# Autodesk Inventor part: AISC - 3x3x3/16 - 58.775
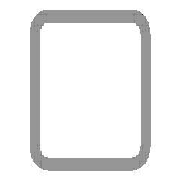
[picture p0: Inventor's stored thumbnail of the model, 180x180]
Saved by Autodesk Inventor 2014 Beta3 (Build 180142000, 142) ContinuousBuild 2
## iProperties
_CCFamilyMember: 9
_CCFamilyDisplayName: ANSI AISC (Square) - Tube
_FrameMemberDoc: Frame Member File
_Version: 15.0.0
_GetPNFromCC: 1
Created: 2011-01
Part Number: AISC - 3x3x3/16 - 58.775
Material: Steel, Mild
Description: Tube
Document SubType Name: Modeling
Standard: ANSI
Designer: Beta-8540w
Standards Organization: ANSI
Language: en-US
Size Designation: 3x3x3/16
Categories: <MemberInstance><Categories><Category DisplayName="Structural Shapes" InternalName="089c4875-fa83-4c05-b084-43b9cc11f5ed" Mnemonic="GRDR"><CategoryParameter Dis
Stock Number: 3x3x3/16
Density: 7.86 g/cm^3
Appearance: Steel
IsCustomPart: 1
G_L: 58.775 in
G_W: 3.000 in
G_H: 3.000 in
+E0C39BE0-1588-4A7D-93DD-AA65CE2CC4A8+CUTDETAIL1: Cut
Author: Beta-8540w
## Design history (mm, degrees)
node "Start plane"
node "End plane"
sketch "Sketch"
  geometry: L1 (-38.1, -28.575)-(-38.1, 28.575); L2 (-28.575, 38.1)-(28.575, 38.1); L3 (38.1, 28.575)-(38.1, -28.575); L4 (28.575, -38.1)-(-28.575, -38.1); L5 (-28.575, 33.337)-(28.575, 33.338); L6 (33.338, 28.575)-(33.338, -28.575); L7 (28.575, -33.337)-(-28.575, -33.338); L8 (-33.338, -28.575)-(-33.338, 28.575); L9 (0, 56.102)-(0, -56.102) reference; L10 (-56.102, 0)-(56.102, 0) reference; A1 r 9.525 centre (-28.575, -28.575) between (-38.1, -28.575) and (-28.575, -38.1); A2 r 9.525 centre (-28.575, 28.575) between (-28.575, 38.1) and (-38.1, 28.575); A3 r 9.525 centre (28.575, 28.575) between (38.1, 28.575) and (28.575, 38.1); A4 r 9.525 centre (28.575, -28.575) between (28.575, -38.1) and (38.1, -28.575); A5 r 4.763 centre (-28.575, 28.575) between (-28.575, 33.337) and (-33.338, 28.575); A6 r 4.763 centre (28.575, 28.575) between (33.338, 28.575) and (28.575, 33.338); A7 r 4.763 centre (28.575, -28.575) between (28.575, -33.337) and (33.338, -28.575); A8 r 4.763 centre (-28.575, -28.575) between (-33.338, -28.575) and (-28.575, -33.338)
  constraints: 16 end point, 16 point on circle, 8 centre point, 8 tangent, 4 parallel, 3 equal radius, 2 perpendicular, 7 other
  dimensions: "d10" = 76.2 distance between parallel lines of L2 L4 (= G_H); "d11" = 76.2 distance between parallel lines of L1 L3 (= G_W); "d12" = 4.7625 distance between parallel lines of L3 L6 (= G_T); "d15" = 38.1 distance between parallel lines of L2 L10 (= 0.5 x d10); "d16" = 38.1 distance between parallel lines of L9 L3 (= 0.5 x d11); "d17" = 9.525 radius of A1 (= G_IR)
extrude "Body" new body sketch "Sketch" stored distance "d3" = 1492.89148 (= G_L); taper "d4" = 0 deg
node "Driven Length"
  sketch "Sketch3"
    geometry: L1 (0, 0)-(10, 0) reference
    constraints: 2 end point, 1 horizontal
  workplane "Work Plane3"
  sketch "Sketch4"
    geometry: L1 (-2, 0)-(12, 0) reference; L2 (-2, 1492.891)-(12, 1492.891) reference
    dimensions: "d19" = 1492.89148 distance between parallel lines of L1 L2 (derived)
workplane "Work Plane4"
split "Split1"
body "Solid1"
other parameters: "G_W" = 76.2 [user parameter; used in 1 equation term], "G_H" = 76.2 [user parameter; used in 1 equation term], "G_T" = 4.7625 [user parameter; used in 1 equation term], "G_IR" = 9.525 [user parameter; used in 1 equation term], "G_L" = 1492.89148 (= d19) [user parameter; used in 1 equation term], "G_OFFSET_START" = 0 [user parameter; used in 1 equation term], "G_OFFSET_END" = -31.10852 [user parameter; used in 1 equation term], "d13" = 0 (computed from G_OFFSET_START), "d14" = 1492.89148 (= G_OFFSET_END + B_L), "B_L" = 1524 [user parameter; used in 1 equation term], "d18" = 90 deg
